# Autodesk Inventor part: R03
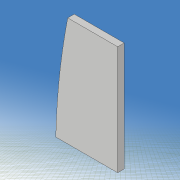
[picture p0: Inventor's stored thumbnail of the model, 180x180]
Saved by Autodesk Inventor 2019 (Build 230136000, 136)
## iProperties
Created: 2021-05
Part Number: R03
Material: 一般
Document SubType Name: Modeling
Designer: kikut
Density: 1 g/cm^3
Appearance: 既定
Mass: 0.0330981 g
Surface Area: 1.28796 cm^2
Volume: 0.0330981 cm^3
Author: kikut
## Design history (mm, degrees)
sketch "スケッチ1"
  geometry: L1 (80, 60)-(-80, 60); L2 (-80, 60)-(-80, -60); L3 (-80, -60)-(80, -60); L4 (80, -60)-(80, 60); L5 (80, 60)-(-80, -60); L6 (-80, 60)-(80, -60); 1 further point
  constraints: 12 end point, 2 midpoint, 2 parallel, 1 horizontal, 1 perpendicular
  dimensions: "d0" = 160 distance of L2.end L3.end; "d1" = 120 distance of L1.end L2.end
extrude "押し出し1" new body sketch "スケッチ1" stored distance "d2" = 0.6; taper "d3" = 0 deg
sketch "スケッチ2"
  geometry: L1 (-140, 0)-(140, 0) reference; L2 (0, -54)-(20, -30); L3 (0, 54)-(20, 30); L4 (0, -3)-(6.514, -3); L5 (6.514, -3)-(16, -6); L6 (16, -6)-(24, -3); L7 (24, -3)-(33.716, -3); L8 (0, 3)-(6.514, 3); L9 (6.514, 3)-(16, 6); L10 (16, 6)-(24, 3); L11 (24, 3)-(33.716, 3); L12 (0, -98)-(0, 98) reference; L13 (-100, -70)-(100, -70); L14 (100, -70)-(100, 70); L15 (100, 70)-(-100, 70); L16 (-100, 70)-(-100, -70); L17 (-100, -70)-(100, 70); L18 (100, -70)-(-100, 70); A1 r 60 centre (54.312, 28.5) between (0, 54) and (0, 3); A2 r 60 centre (54.312, -28.5) between (0, -3) and (0, -54); A3 r 18.111 centre (18, -12) between (20, -30) and (33.716, -3); A4 r 18.111 centre (18, 12) between (33.716, 3) and (20, 30); 1 further point
  constraints: 32 end point, 8 point on circle, 8 symmetric about line, 4 centre point, 3 horizontal, 2 collinear, 2 midpoint, 2 parallel, 1 perpendicular
  dimensions: "d5" = 60 radius of A1; "d6" = 6 distance of L8.start L4.start; "d7" = 108 distance of L3.start L2.start; "d8" = 0 horizontal distance of L3.start L8.start; "d9" = 60 distance of L3.end L2.end; "d10" = 0 horizontal distance of point (0, 0) L3.start; "d11" = 20 horizontal distance of L3.start L3.end; "d12" = 24 distance of A4.centre A3.centre; "d13" = 6 distance of L11.end L7.end; "d14" = 12 distance of L9.end L5.end; "d15" = 16 distance from line of L12 L5.end; "d16" = 24 distance from line of L6.end L12; "d17" = 200 distance of L14.end L15.end; "d18" = 140 distance of L15.end L13.start; "d30" = 18 distance from line of L12 A4.centre
extrude "押し出し2" cut sketch "スケッチ2" stored distance "d19" = 10; taper "d20" = 0 deg
sketch "スケッチ3"
  geometry: L1 (49.705, -17.97)-(33.948, -15.191); L2 (33.948, -15.191)-(34.295, -13.222); L3 (34.295, -13.222)-(50.052, -16); L4 (50.052, -16)-(49.705, -17.97); L5 (49.705, -17.97)-(34.295, -13.222); L6 (33.948, -15.191)-(50.052, -16); L7 (50.052, 16)-(34.295, 13.222); L8 (34.295, 13.222)-(33.948, 15.191); L9 (33.948, 15.191)-(49.705, 17.97); L10 (49.705, 17.97)-(50.052, 16); L11 (50.052, 16)-(33.948, 15.191); L12 (34.295, 13.222)-(49.705, 17.97); L13 (-112, 0)-(112, 0) reference; L14 (0, -84)-(0, 84) reference; 3 further points
  constraints: 24 end point, 4 midpoint, 4 parallel, 2 perpendicular, 2 symmetric about line
  dimensions: "d21" = 2 distance of L3.end L1.start; "d22" = 2 distance of L9.end L7.start; "d23" = 16 distance of L8.end L9.end; "d24" = 42 distance from line of L14 point (42, 15.596); "d26" = 10 deg angle of L7 L13; "d62" = 16 distance from line of L3.end L13
extrude "押し出し3" join sketch "スケッチ3" distance "d27" = 0.6; taper "d28" = 0 deg
fillet "フィレット1" dims "d31" = 2
fillet "フィレット2" dims "d32" = 1
sketch "スケッチ6"
  geometry: L1 (-20, 60)-(80, 60); L2 (80, 60)-(80, -60); L3 (80, -60)-(-20, -60); L4 (-20, -60)-(-20, 60); L5 (-46.168, 0)-(93.832, 0) reference; L6 (0, -84)-(0, 84) reference; L7 (-10, 30)-(0, 30); L8 (0, 30)-(0, 40); L9 (0, 40)-(-10, 40); L10 (-10, 40)-(-10, 30); 1 further point
  constraints: 16 end point, 4 parallel, 2 horizontal, 2 perpendicular, 1 other
  dimensions: "d63" = 120 distance of L3.end L1.start; "d64" = 100 distance of L1.start L1.end; "d65" = 20 distance between parallel lines of L6 L4; "d66" = 10 distance of L8.end L9.end; "d69" = 10 distance between parallel lines of L6 L10; "d72" = 20 distance between parallel lines of L1 L9; "d73" = 10 distance of L9.end L7.start
extrude "押し出し4" cut sketch "スケッチ6" stored distance "d70" = 10; taper "d71" = 0 deg
node "ソリッド1"
